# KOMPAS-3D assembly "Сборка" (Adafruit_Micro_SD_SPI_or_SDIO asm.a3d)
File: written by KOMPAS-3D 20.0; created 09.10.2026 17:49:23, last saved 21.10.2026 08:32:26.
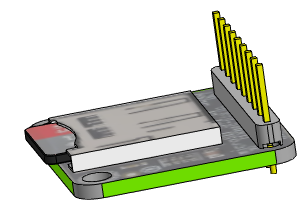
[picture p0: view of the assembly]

Document properties: Полное имя файла: D:\myProjects\Progect_esp32\box_compas\SD card\Adafruit_Micro_SD_SPI_or_SDIO asm.a3d

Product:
- Part/product: Сборка
    Масса: 0.0097836
  - Component [detail]: Деталь  | Масса: 0.00115709; source file: ..\разъемы\pls_9.m3d
  - Component [detail]: Деталь  | Масса: 0.0074136; source file: Adafruit_Micro_SD_SPI_or_SDIO.m3d
  - Component [detail]: Деталь  | Масса: 0.00121292; source file: micro sd.m3d

Referenced files in D:\myProjects\Progect_esp32\box_compas\SD card\: Adafruit_Micro_SD_SPI_or_SDIO.m3d, micro sd.m3d
Referenced files in D:\myProjects\Progect_esp32\box_compas\разъемы\: pls_9.m3d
